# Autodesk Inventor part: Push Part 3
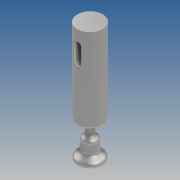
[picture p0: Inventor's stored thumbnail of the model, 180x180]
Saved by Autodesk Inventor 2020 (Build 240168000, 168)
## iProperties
Created: 2019-10
Part Number: Push Part 3
Material: Generic
Document SubType Name: Modeling
Designer: yello
Density: 1 g/cm^3
Appearance: Default
Author: yello
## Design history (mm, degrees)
sketch "Sketch2" dims "d4" = 3
  geometry: L1 (0, 0)-(2, 0); L2 (0, 0)-(0, -26); L3 (0, -26)-(2.5, -26); L4 (2.5, -26)-(2.5, -24); L5 (2.5, -24)-(3.5, -24); L6 (0, -26)-(0, -28); L7 (0, -28)-(2, -28); L8 (2, -24)-(2, 0); L9 (0, -28)-(0, -32.5); L10 (2, -28)-(2, -30); L11 (0, -32.5)-(2, -32.5); L12 (2, -32.5)-(2, -30); L13 (2, -28)-(2, -27.177); L14 (2, -27.177)-(1, -27.177); L15 (1, -27.177)-(1, -26); L16 (2, -24)-(2, -24.823); L17 (2, -24.823)-(1, -24.823); L18 (1, -24.823)-(1, -26); L19 (2, -30.25)-(2, -32.75); L20 (3.5, -32.5)-(3.5, -32.75); L21 (3.5, -32.75)-(2, -32.75); L22 (2, -32.75)-(0, -32.75); L23 (0, -32.75)-(0, -32.5); L24 (2, -30.25)-(2, -32.5); L25 (2, -30.25)-(2, -31.375); L26 (2, -31.375)-(3.5, -31.375); L27 (3.5, -31.375)-(3.5, -32.5); L28 (2, -24)-(2, -23); L29 (2, 0)-(3.5, 0); L30 (3.5, 0)-(3.5, -23.002); L31 (2, -24)-(2, -23.5); L32 (2, -23.5)-(3.5, -23.501); L33 (3.5, -23.501)-(3.5, -23.002)
  constraints: 42 end point, 9 perpendicular, 6 point on line, 6 vertical, 5 horizontal, 3 symmetric about line, 2 midpoint, 1 coincident, 1 horizontal alignment, 14 other
  dimensions: "d0" = 2 distance of L1.start L1.end; "d2" = 26 distance of L1.start L2.end; "d7" = 2 distance of L4.start L4.end; "d8" = 1.5 distance of L5.end L8.start; "d9" = 4.5 distance of L6.end L9.end; "d10" = 2 distance of L7.end L10.end; "d11" = 2.5 distance of L2.end L3.end; "d13" = 2.5 distance of L19.start L19.end; "d15" = 1 distance of L8.start L28.end; "d16" = 1.5 distance of L1.end L29.end; "d25" = 4 distance from line of L10.end L3; "d30" = 0.25 distance from line of L11 L19.end
revolve "Revolution1" sketch "Sketch2" stored, may be unused: angle "d17" = 90 deg
workplane "Work Plane1"
sketch "Sketch3"
  geometry: L1 (0, 0)-(0, -4); L2 (0, -4)-(0, -8); L3 (-1, -4)-(-1, -8); L4 (1, -8)-(1, -4); C1 r 1 at (0, -4); A1 r 1 centre (0, -4) between (1, -4) and (-1, -4); A2 r 1 centre (0, -8) between (-1, -8) and (1, -8); 3 further points
  constraints: 10 end point, 4 point on circle, 4 tangent, 3 centre point, 2 vertical, 1 coincident, 1 concentric, 1 midpoint, 1 parallel
  dimensions: "d19" = 4 distance of L1.start L1.end; "d20" = 2 diameter of C1; "d26" = 4 distance of L2.start L2.end
extrude "Extrusion2" cut sketch "Sketch3" distance "d27" = 10; taper "d28" = 0 deg
body "Solid1"
other parameters: "d18" = 3.5
